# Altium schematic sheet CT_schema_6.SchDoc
size 371 x 336 mm
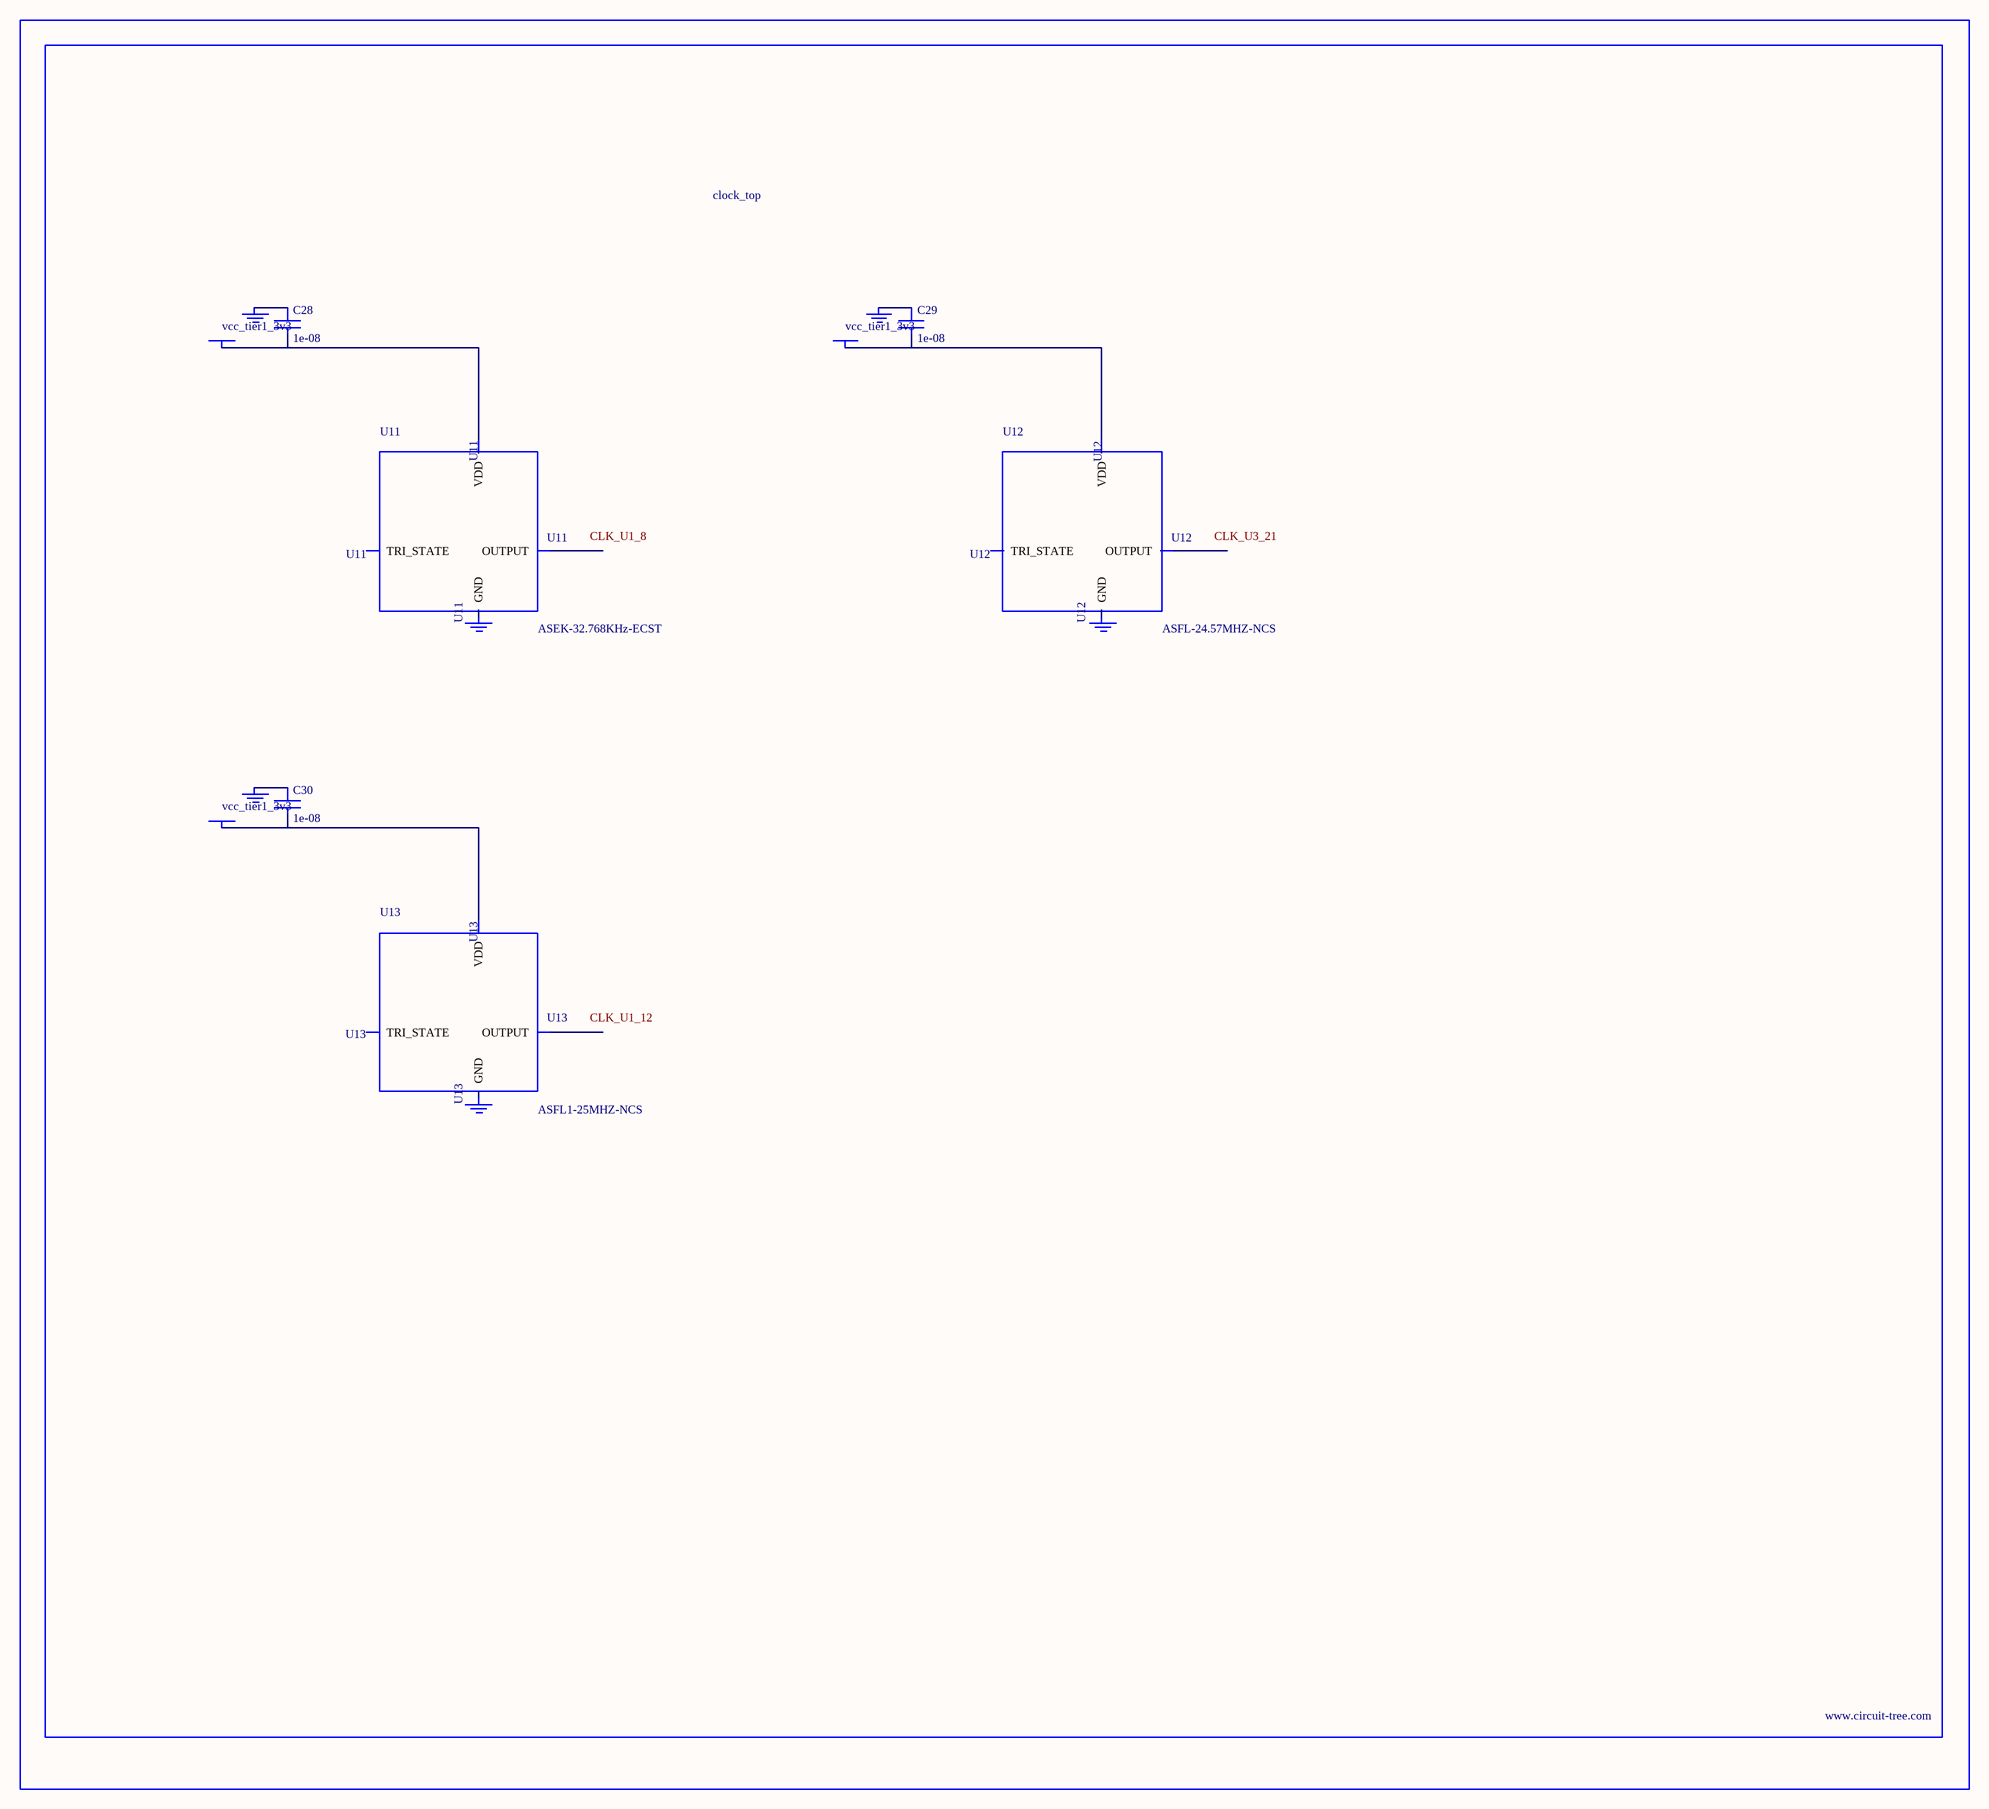
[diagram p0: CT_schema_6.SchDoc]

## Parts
BORDER5  (no value)
C28  1e-08  [C0402]
C29  1e-08  [C0402]
C30  1e-08  [C0402]
GND_INSTANCE_5_0  (no value)
GND_INSTANCE_5_1  (no value)
GND_INSTANCE_5_2  (no value)
GND_INSTANCE_5_3  (no value)
GND_INSTANCE_5_4  (no value)
GND_INSTANCE_5_5  (no value)
POWER_INSTANCE_5_0  vcc_tier1_3v3
POWER_INSTANCE_5_1  vcc_tier1_3v3
POWER_INSTANCE_5_2  vcc_tier1_3v3
U11  ASEK-32.768KHz-ECST  [ASEK]
U12  ASFL-24.57MHZ-NCS  [ASFL1]
U13  ASFL1-25MHZ-NCS  [ASFL1]

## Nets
NetC28_1: C28.1 GND_INSTANCE_5_0.0(GND)
NetC28_2: C28.2 POWER_INSTANCE_5_0.0(PWR) U11.4(VDD)
NetC29_1: C29.1 GND_INSTANCE_5_2.0(GND)
NetC29_2: C29.2 POWER_INSTANCE_5_1.0(PWR) U12.4(VDD)
NetC30_1: C30.1 GND_INSTANCE_5_4.0(GND)
NetC30_2: C30.2 POWER_INSTANCE_5_2.0(PWR) U13.4(VDD)

Not connected (* = marked no-connect by the designer): GND_INSTANCE_5_1 0(GND); GND_INSTANCE_5_3 0(GND); GND_INSTANCE_5_5 0(GND); U11 1(TRI_STATE) 2(GND) 3(OUTPUT); U12 1(TRI_STATE) 2(GND) 3(OUTPUT); U13 1(TRI_STATE) 2(GND) 3(OUTPUT)

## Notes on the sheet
- Labels drawn without touching a wire or pin: CLK_U1_8, CLK_U1_12, CLK_U3_21

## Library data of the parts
BORDER5 = BORDER_PAGE5
C28-C30 = C0402C103K3RAC
GND_INSTANCE_5_0-GND_INSTANCE_5_5 = GND
POWER_INSTANCE_5_0-POWER_INSTANCE_5_2 = PWR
